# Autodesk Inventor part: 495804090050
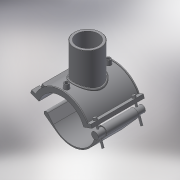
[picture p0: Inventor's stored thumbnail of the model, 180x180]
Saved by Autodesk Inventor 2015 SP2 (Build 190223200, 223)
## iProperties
Created: 2017-07
Part Number: 495804090050
Material: Generic
Description: PLASSON BRANCH SADDLE 90-50
Document SubType Name: Modeling
Designer: KIM
Density: 1 g/cm^3
Appearance: Default
Author: KIM
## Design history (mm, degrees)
derived "495804.ipt"
feature "Solid1::495804.ipt"
feature "Solid2::495804.ipt"
tag "TaggingFeature1"
body "Solid1"
body "Solid2"
other parameters: "d2" = 126, "d3" = 22.5, "d4" = 118, "d5" = 0, "d6" = 0.1, "d8" = 0, "d19" = 6, "d20" = 6, "d21" = 70.8, "d23" = 0, "d24" = 35.4, "d26" = 0, "d27" = 3, "d28" = 3, "d29" = 3, "d31" = 6, "d32" = 0, "d33" = 0, "d34" = 0.6, "d40" = 58.24, "d41" = 55, "d43" = 0, "d45" = 0, "d47" = 149, "d50" = 0, "d70" = 15, "d72" = 0, "d73" = 6, "d75" = 5, "d76" = 0, "d77" = 4.5, "d78" = 75, "d79" = 15, "d80" = 47.2, "d82" = 5 deg, "d84" = 4, "d85" = 14, "d86" = 0, "d87" = 3, "d88" = 0, "d89" = 1, "d90" = 1, "d91" = 94.4, "d92" = 0, "d93" = 0.5, "d94" = 47.36842, "d96" = 114.24, "d97" = 2.36, "d98" = 0, "d102" = 1.5, "d105" = 0, "d109" = -31, "d117" = 0.5, "d120" = 140 deg, "d121" = 24.228, "d122" = 20 deg, "d123" = 224, "d124" = 67.2, "d126" = 0, "d143" = 94.5, "d150" = 16.2, "d159" = 4.4, "d161" = 2.25, "d162" = 70.8, "d163" = 0, "d167" = 18, "d168" = 50.90909, "d173" = 1, "d175" = 45, "d176" = 20 deg, "d177" = 6.3, "d178" = 22, "d180" = 0, "d185" = 38.35, "d186" = 38.35, "d187" = 56, "d188" = 6.6, "d189" = 6.3, "d190" = 0, "d191" = 84, "d200" = 11, "d202" = 0, "d216" = 106.2, "d217" = 0, "d221" = 43.66, "d222" = 6.3, "d223" = 3.78, "d224" = 45, "d225" = 3.78, "d227" = 12.96, "d230" = 55.8, "d236" = 20 deg, "d237" = 63, "d238" = 20 deg, "d239" = 6.3, "B_" = 126, "H_" = 93, "L_" = 118, "d_t" = 6, "H_1" = 82, "d1" = 112, "d148" = 2.25, "d160" = 2.25
